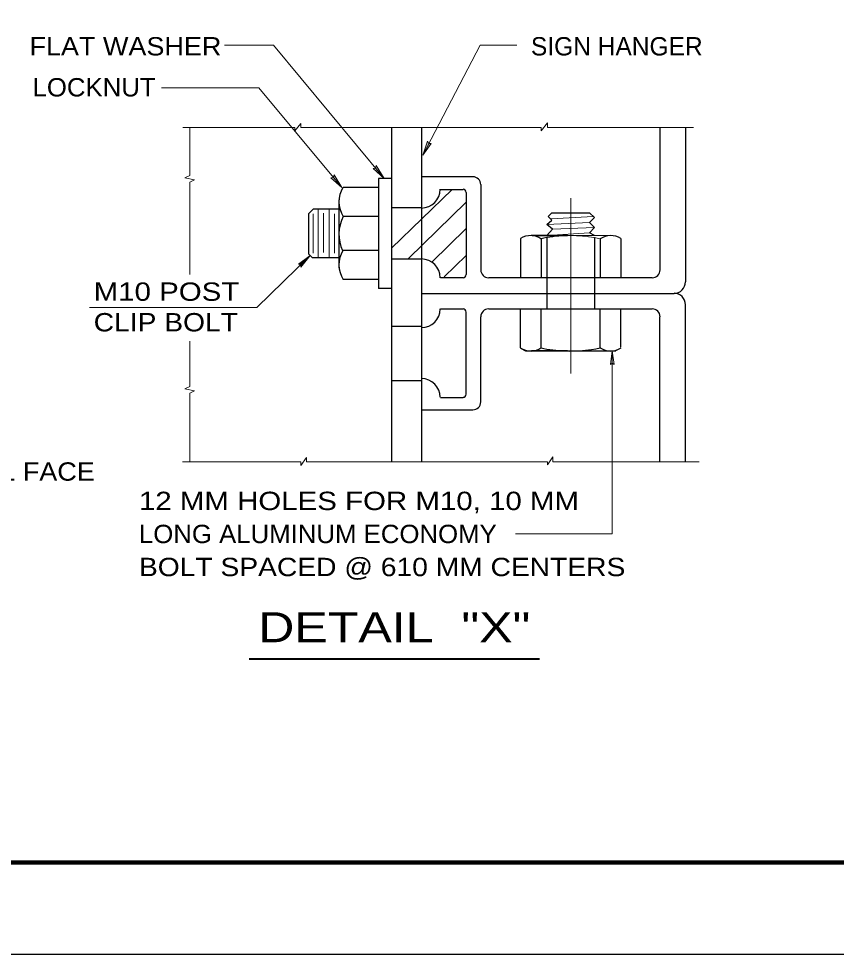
# Model space of a CAD drawing. Extents: x 312601.858 to 312602.699, y 144420.109 to 144420.704.
# Drawn here: x 312602.3741 to 312602.5078, y 144420.1095 to 144420.2624 of the extents above; entities that cross this region are included whole.
import ezdxf

# ---------------------------------------------------------------- set-up
doc = ezdxf.new("R2010")
doc.units = 0
doc.header["$LTSCALE"] = 0.0012
for name, pattern in [('DOT_DASHED', [7.7, 5, -1.2, 0.3, -1.2]), ('LONG_DASHED', [7.5, 6, -1.5]), ('MEDIUM_DASHED', [4.5, 3, -1.5])]:
    doc.linetypes.add(name, pattern=pattern)
for name, color, linetype, lineweight in [('1', 7, 'Continuous', 13), ('2', 7, 'Continuous', 13), ('39', 7, 'Continuous', 13)]:
    doc.layers.add(name, color=color, linetype=linetype, lineweight=lineweight)

msp = doc.modelspace()

# ---------------------------------------------------------------- hatches: boundary and pattern name
at = {"layer": '39'}
for points in [[(312602.4412, 144420.242), (312602.4416, 144420.242), (312602.4402, 144420.2401), (312602.441, 144420.2424)], [(312602.4325, 144420.238), (312602.4326, 144420.2384), (312602.4339, 144420.2363), (312602.4321, 144420.2379)], [(312602.4256, 144420.2365), (312602.4257, 144420.2369), (312602.427, 144420.2348), (312602.4252, 144420.2364)], [(312602.4202, 144420.2222), (312602.4199, 144420.2223), (312602.4218, 144420.2237), (312602.4203, 144420.2218)]]:
    msp.add_hatch(color=256, dxfattribs=at).paths.add_polyline_path(points)

# ---------------------------------------------------------------- linework, layer by layer
at = {"layer": '1'}
for p, q in [((312602.4078, 144420.2581), (312602.4158, 144420.2581)), ((312602.4496, 144420.2581), (312602.4556, 144420.2581)), ((312602.3975, 144420.2511), (312602.4134, 144420.2511)), ((312602.401, 144420.2446), (312602.4193, 144420.2446)), ((312602.4021, 144420.2446), (312602.4021, 144420.2368)), ((312602.4193, 144420.2441), (312602.4203, 144420.2453)), ((312602.4193, 144420.2441), (312602.4193, 144420.2446)), ((312602.4203, 144420.2446), (312602.4203, 144420.2453)), ((312602.4203, 144420.2446), (312602.4596, 144420.2446)), ((312602.4596, 144420.2441), (312602.4606, 144420.2454)), ((312602.4596, 144420.2441), (312602.4596, 144420.2446)), ((312602.4606, 144420.2446), (312602.4606, 144420.2454)), ((312602.4606, 144420.2446), (312602.4845, 144420.2446)), ((312602.4013, 144420.2364), (312602.4021, 144420.2368)), ((312602.4013, 144420.2364), (312602.4029, 144420.2361)), ((312602.4021, 144420.2357), (312602.4029, 144420.2361)), ((312602.4021, 144420.2357), (312602.4021, 144420.2206)), ((312602.4351, 144420.2249), (312602.445, 144420.2345)), ((312602.4379, 144420.2232), (312602.4473, 144420.2324)), ((312602.4223, 144420.2305), (312602.4223, 144420.2241)), ((312602.4231, 144420.2313), (312602.4231, 144420.2233)), ((312602.424, 144420.2306), (312602.424, 144420.2242)), ((312602.4249, 144420.2313), (312602.4249, 144420.2233)), ((312602.4258, 144420.2305), (312602.4258, 144420.2241)), ((312602.4605, 144420.2288), (312602.4675, 144420.2291)), ((312602.4612, 144420.2297), (312602.4681, 144420.2301)), ((312602.4417, 144420.2226), (312602.4473, 144420.2281)), ((312602.4605, 144420.227), (312602.4675, 144420.2274)), ((312602.4614, 144420.228), (312602.4683, 144420.2283)), ((312602.4649, 144420.227), (312602.4708, 144420.227)), ((312602.4437, 144420.2202), (312602.4473, 144420.2237)), ((312602.4131, 144420.2152), (312602.3857, 144420.2152)), ((312602.4021, 144420.2097), (312602.4021, 144420.2023)), ((312602.4649, 144420.2081), (312602.4708, 144420.2081)), ((312602.4725, 144420.2085), (312602.4718, 144420.2081)), ((312602.4013, 144420.2019), (312602.4021, 144420.2023)), ((312602.4013, 144420.2019), (312602.4029, 144420.2016)), ((312602.4021, 144420.2012), (312602.4029, 144420.2016)), ((312602.4021, 144420.2012), (312602.4021, 144420.19)), ((312602.4203, 144420.1894), (312602.4212, 144420.1907)), ((312602.4212, 144420.19), (312602.4212, 144420.1907)), ((312602.4606, 144420.1895), (312602.4615, 144420.1908)), ((312602.4615, 144420.19), (312602.4615, 144420.1908)), ((312602.4009, 144420.19), (312602.4203, 144420.19)), ((312602.4203, 144420.1894), (312602.4203, 144420.19)), ((312602.4212, 144420.19), (312602.4606, 144420.19)), ((312602.4606, 144420.1895), (312602.4606, 144420.19)), ((312602.4615, 144420.19), (312602.4854, 144420.19))]:
    msp.add_line(p, q, dxfattribs=at)
at = {"layer": '1', "lineweight": 25}
for p, q in [((312602.4351, 144420.2446), (312602.4351, 144420.19)), ((312602.44, 144420.2446), (312602.44, 144420.19)), ((312602.479, 144420.2446), (312602.479, 144420.2214)), ((312602.4832, 144420.2446), (312602.4832, 144420.2194)), ((312602.44, 144420.2366), (312602.4484, 144420.2366)), ((312602.433, 144420.2363), (312602.433, 144420.2183)), ((312602.4497, 144420.2353), (312602.4497, 144420.2214)), ((312602.4431, 144420.2345), (312602.4468, 144420.2345)), ((312602.4473, 144420.234), (312602.4473, 144420.2206)), ((312602.4265, 144420.2328), (312602.4265, 144420.2217)), ((312602.4215, 144420.2305), (312602.4215, 144420.224)), ((312602.4607, 144420.2301), (312602.4613, 144420.2307)), ((312602.4613, 144420.2307), (312602.4675, 144420.2307)), ((312602.4683, 144420.2299), (312602.4675, 144420.2307)), ((312602.4683, 144420.227), (312602.4675, 144420.2274)), ((312602.4562, 144420.2265), (312602.4562, 144420.2201)), ((312602.4639, 144420.227), (312602.458, 144420.227)), ((312602.4596, 144420.2265), (312602.4596, 144420.2201)), ((312602.4692, 144420.2265), (312602.4692, 144420.2201)), ((312602.4726, 144420.2265), (312602.4726, 144420.2201)), ((312602.4431, 144420.2201), (312602.4468, 144420.2201)), ((312602.451, 144420.2201), (312602.4777, 144420.2201)), ((312602.44, 144420.2175), (312602.4813, 144420.2175)), ((312602.4832, 144420.19), (312602.4832, 144420.2157)), ((312602.4431, 144420.215), (312602.4468, 144420.215)), ((312602.4473, 144420.201), (312602.4473, 144420.2145)), ((312602.4497, 144420.1998), (312602.4497, 144420.2137)), ((312602.451, 144420.215), (312602.4777, 144420.215)), ((312602.4562, 144420.2086), (312602.4562, 144420.215)), ((312602.4596, 144420.2086), (312602.4596, 144420.215)), ((312602.4692, 144420.2086), (312602.4692, 144420.215)), ((312602.4726, 144420.2087), (312602.4726, 144420.215)), ((312602.479, 144420.19), (312602.479, 144420.2137)), ((312602.44, 144420.2121), (312602.4351, 144420.2121)), ((312602.4563, 144420.2085), (312602.457, 144420.2081)), ((312602.457, 144420.2081), (312602.458, 144420.2081)), ((312602.4639, 144420.2081), (312602.458, 144420.2081)), ((312602.4639, 144420.2081), (312602.4718, 144420.2081)), ((312602.44, 144420.2032), (312602.4351, 144420.2032)), ((312602.4431, 144420.2005), (312602.4468, 144420.2005)), ((312602.44, 144420.1985), (312602.4484, 144420.1985))]:
    msp.add_line(p, q, dxfattribs=at)
at = {"layer": '1', "linetype": 'DOT_DASHED'}
msp.add_line((312602.4644, 144420.2044), (312602.4644, 144420.2331), dxfattribs=at)
at = {"layer": '1', "linetype": 'MEDIUM_DASHED', "lineweight": 25}
for p, q in [((312602.44, 144420.2315), (312602.4351, 144420.2315)), ((312602.44, 144420.2231), (312602.4351, 144420.2231))]:
    msp.add_line(p, q, dxfattribs=at)
at = {"layer": '1', "linetype": 'LONG_DASHED', "lineweight": 25}
for p, q in [((312602.4605, 144420.2266), (312602.4605, 144420.215)), ((312602.4683, 144420.2266), (312602.4683, 144420.215))]:
    msp.add_line(p, q, dxfattribs=at)
at = {"layer": '1', "lineweight": 25}
for points in [[(312602.4605, 144420.227), (312602.4614, 144420.228), (312602.4605, 144420.2288), (312602.4613, 144420.2295), (312602.4607, 144420.2301)], [(312602.4675, 144420.2274), (312602.4683, 144420.2283), (312602.4675, 144420.2291), (312602.4683, 144420.2299)], [(312602.4639, 144420.227), (312602.4581, 144420.227), (312602.4639, 144420.227)], [(312602.4639, 144420.2081), (312602.4581, 144420.2081), (312602.4639, 144420.2081)]]:
    msp.add_lwpolyline(points, dxfattribs=at)
at = {"layer": '1'}
for points in [[(312602.4649, 144420.227), (312602.4707, 144420.227), (312602.4649, 144420.227)], [(312602.4712, 144420.2081), (312602.4712, 144420.1782), (312602.4554, 144420.1782)], [(312602.4649, 144420.2081), (312602.4707, 144420.2081), (312602.4649, 144420.2081)]]:
    msp.add_lwpolyline(points, dxfattribs=at)
at = {"layer": '1', "linetype": 'LONG_DASHED', "lineweight": 25}
msp.add_lwpolyline([(312602.4581, 144420.2081), (312602.4639, 144420.2081), (312602.4581, 144420.2081)], dxfattribs=at)
at = {"layer": '1'}
msp.add_lwpolyline([(312602.4709, 144420.2059), (312602.4712, 144420.2081), (312602.4715, 144420.2059), (312602.4712, 144420.2061)], close=True, dxfattribs=at)
at = {"layer": '1', "lineweight": 25}
for centre, radius, start, end in [((312602.448415, 144420.235295), 0.001275, 0, 90), ((312602.44, 144420.23453), 0.00306, 270, 0), ((312602.4468, 144420.23402), 0.00051, 0, 90), ((312602.45785, 144420.22399), 0.002975, 88.37341, 123.68467), ((312602.45785, 144420.22399), 0.002975, 55.64684, 86.74614), ((312602.464395, 144420.203696), 0.023269, 92.30038, 102.01801), ((312602.47094, 144420.22399), 0.002975, 56.08356, 124.66567), ((312602.44, 144420.22008), 0.00306, 0, 90), ((312602.450965, 144420.221355), 0.001275, 180, 270), ((312602.47774, 144420.221355), 0.001275, 270, 0), ((312602.4468, 144420.22059), 0.00051, 270, 0), ((312602.48131, 144420.2194), 0.00187, 270, 0), ((312602.48131, 144420.21566), 0.00187, 0, 90), ((312602.44, 144420.21498), 0.00306, 270, 0), ((312602.4468, 144420.21447), 0.00051, 0, 90), ((312602.450965, 144420.213705), 0.001275, 90, 180), ((312602.47774, 144420.213705), 0.001275, 0, 90), ((312602.45785, 144420.21107), 0.002975, 235.15009, 271.62659), ((312602.45785, 144420.21107), 0.002975, 273.25386, 304.35316), ((312602.464395, 144420.231364), 0.023269, 257.98199, 267.69962), ((312602.464395, 144420.231364), 0.023269, 267.87557, 281.99656), ((312602.47094, 144420.21107), 0.002975, 235.33433, 304.84991), ((312602.44, 144420.20053), 0.00306, 0, 90), ((312602.4468, 144420.20104), 0.00051, 270, 0), ((312602.448415, 144420.199765), 0.001275, 270, 0)]:
    msp.add_arc(centre, radius, start, end, dxfattribs=at)
at = {"layer": '1'}
for centre, radius, start, end in [((312602.464395, 144420.203696), 0.023269, 78.00344, 92.12443), ((312602.464395, 144420.203696), 0.023269, 77.98199, 87.69962), ((312602.47094, 144420.22399), 0.002975, 93.25386, 124.35316), ((312602.464395, 144420.231364), 0.023269, 272.30038, 282.01801), ((312602.47094, 144420.21107), 0.002975, 235.64684, 266.74614)]:
    msp.add_arc(centre, radius, start, end, dxfattribs=at)
at = {"layer": '2'}
for p, q in [((312602.4339, 144420.2363), (312602.4158, 144420.2581)), ((312602.4402, 144420.2401), (312602.4496, 144420.2581)), ((312602.427, 144420.2348), (312602.4134, 144420.2511)), ((312602.4131, 144420.2152), (312602.4218, 144420.2237))]:
    msp.add_line(p, q, dxfattribs=at)
at = {"layer": '2', "lineweight": 25}
for p, q in [((312602.4351, 144420.2363), (312602.433, 144420.2363)), ((312602.433, 144420.2348), (312602.4272, 144420.2348)), ((312602.4215, 144420.2305), (312602.4223, 144420.2313)), ((312602.4265, 144420.2313), (312602.4223, 144420.2313)), ((312602.433, 144420.2301), (312602.4272, 144420.2301)), ((312602.433, 144420.2245), (312602.4271, 144420.2245)), ((312602.4215, 144420.224), (312602.4222, 144420.2233)), ((312602.4265, 144420.2233), (312602.4222, 144420.2233)), ((312602.433, 144420.2198), (312602.4272, 144420.2198)), ((312602.4351, 144420.2183), (312602.433, 144420.2183))]:
    msp.add_line(p, q, dxfattribs=at)
at = {"layer": '2', "lineweight": 40}
msp.add_line((312602.4118, 144420.1578), (312602.4593, 144420.1578), dxfattribs=at)
at = {"layer": '2', "lineweight": 25}
for centre, radius, start, end in [((312602.43089, 144420.232481), 0.004392, 148.13408, 212.83301), ((312602.432834, 144420.227198), 0.006338, 152.75314, 205.20079), ((312602.43089, 144420.222181), 0.004392, 148.13408, 212.83301)]:
    msp.add_arc(centre, radius, start, end, dxfattribs=at)
at = {"layer": '39', "lineweight": 25}
msp.add_line((312602.452, 144420.1245), (312602.6838, 144420.1245), dxfattribs=at)
msp.add_lwpolyline([(312601.8578, 144420.1095), (312602.6988, 144420.1095), (312602.6988, 144420.7035)], dxfattribs=at)
at = {"layer": '39', "lineweight": 158}
msp.add_lwpolyline([(312601.9088, 144420.1245), (312602.6838, 144420.1245), (312602.6838, 144420.6645)], dxfattribs=at)
at = {"layer": '39'}
for points in [[(312602.4412, 144420.242), (312602.4416, 144420.242), (312602.4402, 144420.2401), (312602.441, 144420.2424)], [(312602.4325, 144420.238), (312602.4326, 144420.2384), (312602.4339, 144420.2363), (312602.4321, 144420.2379)], [(312602.4256, 144420.2365), (312602.4257, 144420.2369), (312602.427, 144420.2348), (312602.4252, 144420.2364)], [(312602.4202, 144420.2222), (312602.4199, 144420.2223), (312602.4218, 144420.2237), (312602.4203, 144420.2218)]]:
    msp.add_lwpolyline(points, close=True, dxfattribs=at)

# ---------------------------------------------------------------- texts
at = {"layer": '2'}
for s, height, width, p in [('FLAT WASHER', 0.003, 1.1, (312602.3759, 144420.2564)), ('LOCKNUT', 0.003, 1.05, (312602.3764, 144420.2497)), ('M10 POST ', 0.003, 1.2, (312602.3864, 144420.2163)), ('CLIP BOLT', 0.003, 1.15, (312602.3864, 144420.2113)), ('SIGN PANEL FACE', 0.003, 1.1, (312602.3471, 144420.1869)), ('12 MM HOLES FOR M10, 10 MM ', 0.003, 1.2, (312602.3938, 144420.1821)), ('LONG ALUMINUM ECONOMY', 0.003, 1.05, (312602.3938, 144420.1767)), ('BOLT SPACED @ 610 MM CENTERS', 0.003, 1.15, (312602.3938, 144420.1713)), ('DETAIL  "X"', 0.0049, 1.25, (312602.4133, 144420.1605))]:
    msp.add_text(s, height=height, dxfattribs=dict(at, width=width)).set_placement(p)
msp.add_text('SIGN HANGER', height=0.003, dxfattribs=at).set_placement((312602.4579, 144420.2564))

doc.saveas('drawing.dxf')
